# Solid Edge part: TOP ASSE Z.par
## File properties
Subject: TOP ASSE Z
Author: f_grande
Template: Normal.par
Last saved by: f_grande
Revision: 7
Application: Solid Edge
Densità: 750,000 kg/m^3
Precisione: 0,990
Tipo di contenuto documento: 0
Document Number: KR0123
Material: MDF
Stile della faccia: Marroncino
Coef. of Thermal Exp: 0.0
Thermal Conductivity: 0.0
Specific Heat: 0.0
Modulus of Elasticity: 0.0
Poisson's Ratio: 0.0
Yield Stress: 0.0
Ultimate Stress: 0.0
Elongation: 0.0
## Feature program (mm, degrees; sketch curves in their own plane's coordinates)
sketch for "unnamed Protrusion 1" plane through (0, 0, 0) normal (0, -1, 0) x-axis (1, 0, 0)
  line (-32.0698, 29.0952) -> (96.9302, 29.0952)
  line (96.9302, 29.0952) -> (96.9302, -104.9048)
  line (96.9302, -104.9048) -> (-32.0698, -104.9048)
  line (-32.0698, -104.9048) -> (-32.0698, 29.0952)
  dimension (linear) = 32.0698
  dimension (linear) = 32.0698
extrude "unnamed Protrusion 1" add finite 19 along +normal
sketch for "Foro_1" plane through (32.4302, -19, -37.9048) normal (0, -1, 0) x-axis (1, 0, 0)
  hole centre (0, -38) bore radius 10
hole "Foro_1" diameter 20 through
sketch for "Foro_2" plane through (32.4302, -19, -37.9048) normal (0, -1, 0) x-axis (1, 0, 0)
  hole centre (41.5, -34) bore radius 6
hole "Foro_2" diameter 12 through
sketch for "unnamed Hole 1" plane through (32.4302, -19, -37.9048) normal (0, -1, 0) x-axis (1, 0, 0)
  hole centre (-41.5, -34) bore radius 6
hole "unnamed Hole 1" through
pattern "unnamed Pattern 1" of "Foro_2", "unnamed Hole 1"
sketch for "Foro_8" plane through (32.4302, -19, -37.9048) normal (0, -1, 0) x-axis (1, 0, 0)
  hole centre (0, -14.6308) bore radius 2.25
hole "Foro_8" diameter 4.5 through
sketch for "unnamed Hole 2" plane through (32.4302, -19, -37.9048) normal (0, -1, 0) x-axis (1, 0, 0)
  hole centre (23.57, -38.2008) bore radius 2.25
hole "unnamed Hole 2" through
sketch for "unnamed Hole 3" plane through (32.4302, -19, -37.9048) normal (0, -1, 0) x-axis (1, 0, 0)
  hole centre (-23.57, -38.2008) bore radius 2.25
hole "unnamed Hole 3" through
sketch for "unnamed Hole 4" plane through (32.4302, -19, -37.9048) normal (0, -1, 0) x-axis (1, 0, 0)
hole "unnamed Hole 4" through
pattern "unnamed Pattern 2" of "Foro_8", "unnamed Hole 2", "unnamed Hole 3", "unnamed Hole 4"
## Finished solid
Body 1: solid body, 13 faces, 26 edges, 8 vertices.
  Faces by surface: cylinder 7, plane 6
  Edges by curve: circle 14, line 12
Bounding box of the edges (mm): 129.000 x 19.000 x 134.000, from (-32.0698, -19, -104.9048) to (96.9302, 0, 29.0952).
Cylindrical faces by radius (mm): R2.25 x4, R6 x2, R10 x1
Planar faces by outward normal: +x 1, +y 1, +z 1, -x 1, -y 1, -z 1
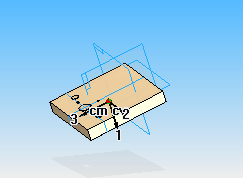
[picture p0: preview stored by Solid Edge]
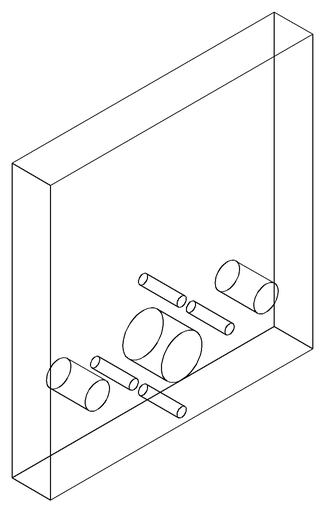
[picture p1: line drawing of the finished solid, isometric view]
